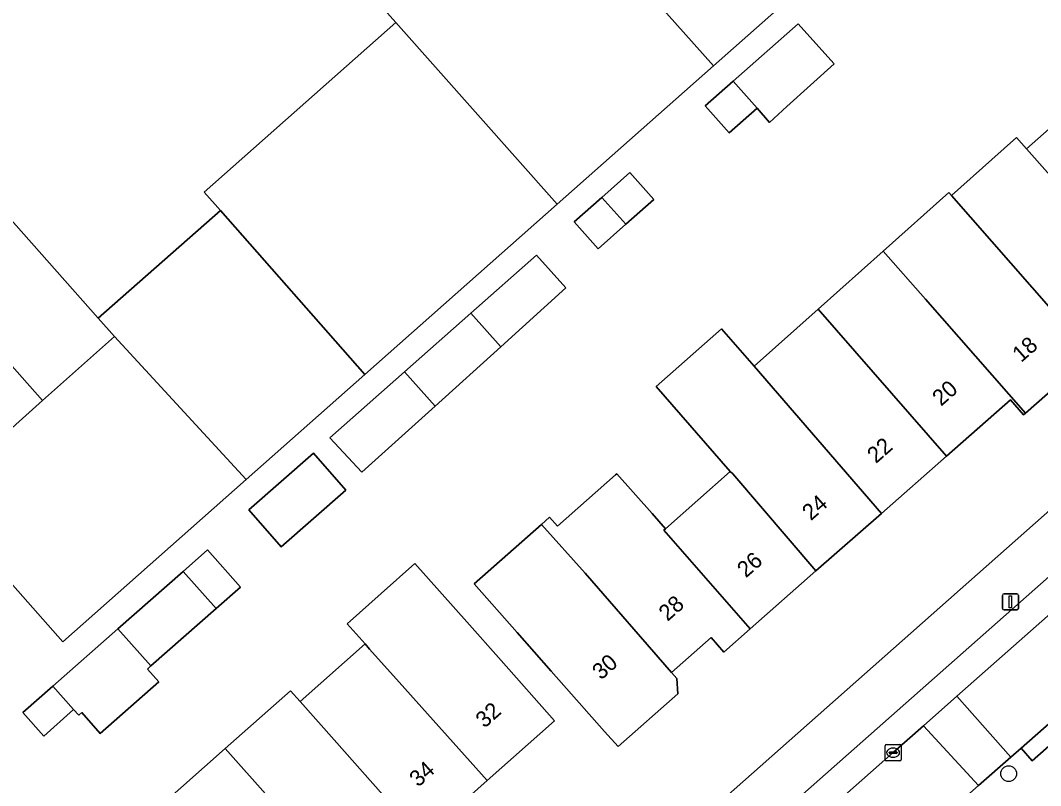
# Model space of a CAD drawing. Extents: x 157320 to 158835, y 386650 to 388491.
# Drawn here: x 157506.5 to 157569.8, y 387760.4 to 387807.9 of the extents above; entities that cross this region are included whole.
import ezdxf

# ---------------------------------------------------------------- set-up
doc = ezdxf.new("R2010")
doc.units = 0
for name, color, linetype in [('IMGEO_Boom', 7, 'Continuous'), ('IMGEO_Erf', 7, 'Continuous'), ('IMGEO_Kolk', 7, 'Continuous'), ('IMGEO_Lichtmast', 7, 'Continuous'), ('IMGEO_Pand', 7, 'Continuous'), ('IMGEO_Pand_nummerreeks', 7, 'Continuous'), ('IMGEO_Parkeervlak_open', 7, 'Continuous'), ('IMGEO_Rijbaan_lokaal_open', 7, 'Continuous'), ('IMGEO_Voetpad_open', 7, 'Continuous')]:
    doc.layers.add(name, color=color, linetype=linetype)

msp = doc.modelspace()

# ---------------------------------------------------------------- linework, layer by layer
at = {"layer": 'IMGEO_Boom'}
msp.add_circle((157567.808, 387761.126), 0.489, dxfattribs=at)
at = {"layer": 'IMGEO_Erf'}
for points in [[(157500.442, 387801.652), (157511.299, 387789.421), (157518.874, 387796.096), (157517.869, 387797.236), (157529.765, 387807.772), (157526.254, 387811.719), (157534.337, 387818.87), (157533.065, 387820.308), (157534.713, 387821.765), (157545.368, 387809.725), (157550.727, 387814.47), (157552.856, 387816.356), (157556.966, 387811.71), (157549.48, 387805.08), (157539.79, 387796.498), (157527.844, 387785.918), (157520.476, 387779.393), (157509.086, 387769.305), (157501.142, 387778.301), (157507.844, 387784.293), (157495.97, 387797.689)], [(157572.95, 387787.111), (157568.862, 387783.508), (157568.739, 387783.4), (157567.916, 387784.335), (157563.943, 387780.84), (157559.906, 387777.288), (157555.846, 387773.716), (157551.763, 387770.125), (157550.122, 387768.681), (157549.34, 387769.574), (157546.882, 387767.406), (157547.215, 387767.03), (157547.277, 387766.084), (157543.567, 387762.807), (157542.728, 387763.743), (157539.419, 387767.492), (157537.304, 387769.887), (157534.627, 387772.919), (157538.801, 387776.604), (157539.311, 387777.054), (157539.796, 387776.504), (157543.397, 387779.685), (157543.479, 387779.757), (157545.672, 387777.275), (157546.499, 387776.339), (157550.514, 387779.884), (157545.936, 387785.18), (157549.99, 387788.759), (157552.01, 387786.423), (157555.986, 387789.974), (157560.024, 387793.581), (157564.098, 387797.219), (157564.258, 387797.039), (157566.759, 387799.27), (157568.287, 387800.633), (157568.92, 387799.92), (157572.962, 387803.488)], [(157509.624, 387726.538), (157507.154, 387731.474), (157527.921, 387750), (157537.423, 387758.476), (157542.489, 387752.818), (157588.712, 387793.729)], [(157515.137, 387759.104), (157519.176, 387762.687), (157523.225, 387766.279), (157523.826, 387765.604), (157527.855, 387769.189), (157526.745, 387770.437), (157528.855, 387772.315), (157530.946, 387774.176), (157534.17, 387770.552), (157536.304, 387768.154), (157539.627, 387764.418), (157535.442, 387760.694), (157531.389, 387757.088)]]:
    msp.add_lwpolyline(points, dxfattribs=at)
for points in [[(157548.977, 387802.592), (157550.708, 387804.123), (157554.75, 387807.699), (157556.394, 387805.856), (157556.976, 387805.204), (157554.046, 387802.551), (157552.964, 387801.571), (157552.192, 387802.444), (157550.462, 387800.914)], [(157540.834, 387795.391), (157542.556, 387796.914), (157544.295, 387798.451), (157545.779, 387796.773), (157544.049, 387795.242), (157542.319, 387793.712)], [(157532.211, 387783.956), (157527.667, 387779.841), (157525.677, 387781.984), (157530.308, 387786.08), (157534.425, 387789.722), (157538.491, 387793.318), (157540.311, 387791.292), (157536.279, 387787.64)], [(157520.645, 387777.504), (157524.65, 387781.022), (157526.661, 387778.732), (157522.656, 387775.215)], [(157511.408, 387763.621), (157510.266, 387764.917), (157510.082, 387764.754), (157509.766, 387765.108), (157507.925, 387763.459), (157506.61, 387764.928), (157508.467, 387766.564), (157512.511, 387770.125), (157516.556, 387773.687), (157518.078, 387775.027), (157520.119, 387772.709), (157518.619, 387771.388), (157514.568, 387767.821), (157514.342, 387767.622), (157515.045, 387766.823)]]:
    msp.add_lwpolyline(points, close=True, dxfattribs=at)
at = {"layer": 'IMGEO_Kolk'}
for p, q in [((157560.211, 387762.932), (157561.063, 387762.932)), ((157560.136, 387762.006), (157560.136, 387762.858)), ((157560.395, 387762.426), (157560.395, 387762.438)), ((157560.833, 387762.389), (157560.435, 387762.389)), ((157560.438, 387762.475), (157560.836, 387762.475)), ((157560.624, 387762.712), (157560.649, 387762.712)), ((157560.879, 387762.438), (157560.879, 387762.426)), ((157561.137, 387762.858), (157561.137, 387762.006)), ((157561.063, 387761.932), (157560.211, 387761.932)), ((157560.647, 387762.152), (157560.622, 387762.152))]:
    msp.add_line(p, q, dxfattribs=at)
for points in [[(157560.211, 387762.932), (157561.063, 387762.932)], [(157560.136, 387762.006), (157560.136, 387762.858)], [(157561.137, 387762.858), (157561.137, 387762.006)], [(157561.063, 387761.932), (157560.211, 387761.932)]]:
    msp.add_lwpolyline(points, dxfattribs=at)
for centre, radius, start, end in [((157560.213, 387762.856), 0.0765, 91.55205, 178.44795), ((157560.213, 387762.856), 0.0765, 91.55205, 178.44795), ((157561.061, 387762.856), 0.0765, 1.55205, 88.44795), ((157561.061, 387762.856), 0.0765, 1.55205, 88.44795), ((157560.435, 387762.435), 0.0403, 85.87752, 175.75265), ((157560.432, 387762.425), 0.0366, 178.93798, 274.71019), ((157560.836, 387762.432), 0.043, 264.86636, 352.45326), ((157560.84, 387762.437), 0.0386, 1.73085, 96.63898), ((157560.213, 387762.008), 0.0765, 181.55205, 268.44795), ((157560.213, 387762.008), 0.0765, 181.55205, 268.44795), ((157561.061, 387762.008), 0.0765, 271.55205, 358.44795), ((157561.061, 387762.008), 0.0765, 271.55205, 358.44795)]:
    msp.add_arc(centre, radius, start, end, dxfattribs=at)
for centre, major_axis, ratio, start_param, end_param in [((157560.623, 387762.432), (-0.387, 0.002), 0.722429, 4.712389, 7.853982), ((157560.648, 387762.432), (-0.39, 0.002), 0.717154, 1.570796, 4.712389)]:
    msp.add_ellipse(centre, major_axis=major_axis, ratio=ratio, start_param=start_param, end_param=end_param, dxfattribs=at)
at = {"layer": 'IMGEO_Lichtmast'}
for p, q in [((157567.422, 387771.394), (157567.422, 387772.194)), ((157567.422, 387772.194), (157567.422, 387771.394)), ((157567.522, 387772.294), (157568.312, 387772.294)), ((157568.312, 387772.294), (157567.522, 387772.294)), ((157568.412, 387772.194), (157568.412, 387771.394)), ((157568.412, 387771.394), (157568.412, 387772.194)), ((157568.312, 387771.294), (157567.522, 387771.294)), ((157567.522, 387771.294), (157568.312, 387771.294))]:
    msp.add_line(p, q, dxfattribs=at)
msp.add_lwpolyline([(157567.842, 387772.169), (157567.992, 387772.169), (157567.992, 387771.419), (157567.842, 387771.419), (157567.842, 387772.169)], dxfattribs=at)
for centre, start, end in [((157567.522, 387772.194), 90, 180), ((157567.522, 387772.194), 90, 180), ((157568.312, 387772.194), 0, 90), ((157568.312, 387772.194), 360, 90), ((157567.522, 387771.394), 180, 270), ((157567.522, 387771.394), 180, 270), ((157568.312, 387771.394), 270, 0), ((157568.312, 387771.394), 270, 0)]:
    msp.add_arc(centre, 0.1, start, end, dxfattribs=at)
at = {"layer": 'IMGEO_Pand'}
for points in [[(157539.79, 387796.498), (157549.48, 387805.08), (157545.368, 387809.725), (157534.713, 387821.765), (157533.065, 387820.308), (157534.337, 387818.87), (157526.254, 387811.719), (157529.765, 387807.772)], [(157556.966, 387811.71), (157552.856, 387816.356), (157550.727, 387814.47), (157545.368, 387809.725), (157549.48, 387805.08)], [(157498.67, 387803.655), (157495.802, 387806.846), (157493.105, 387804.497), (157490.773, 387807.173), (157488.177, 387810.15), (157482.553, 387805.18), (157482.982, 387804.665), (157482.95, 387803.667), (157484.292, 387802.163), (157485.262, 387802.107), (157490.175, 387796.56), (157493.967, 387799.899), (157495.97, 387797.689), (157507.844, 387784.293), (157512.304, 387788.281), (157511.299, 387789.421), (157500.442, 387801.652), (157500, 387802.138)], [(157539.79, 387796.498), (157529.765, 387807.772), (157517.869, 387797.236), (157518.874, 387796.096), (157527.844, 387785.918)], [(157556.976, 387805.204), (157556.394, 387805.856), (157554.75, 387807.699), (157550.708, 387804.123), (157552.192, 387802.444), (157552.964, 387801.571), (157554.046, 387802.551)], [(157550.708, 387804.123), (157548.977, 387802.592), (157550.462, 387800.914), (157552.192, 387802.444)], [(157577.015, 387790.693), (157581.065, 387794.262), (157575.712, 387800.377), (157572.962, 387803.488), (157568.92, 387799.92), (157571.687, 387796.8)], [(157571.687, 387796.8), (157568.92, 387799.92), (157568.287, 387800.633), (157566.759, 387799.27), (157564.258, 387797.039), (157572.95, 387787.111), (157577.015, 387790.693)], [(157542.556, 387796.914), (157544.049, 387795.242), (157545.779, 387796.773), (157544.295, 387798.451)], [(157560.024, 387793.581), (157562.656, 387790.603), (157568.862, 387783.508), (157572.95, 387787.111), (157564.258, 387797.039), (157564.098, 387797.219)], [(157544.049, 387795.242), (157542.556, 387796.914), (157540.834, 387795.391), (157542.319, 387793.712)], [(157512.304, 387788.281), (157520.476, 387779.393), (157527.844, 387785.918), (157518.874, 387796.096), (157511.299, 387789.421)], [(157536.279, 387787.64), (157540.311, 387791.292), (157538.491, 387793.318), (157534.425, 387789.722)], [(157555.986, 387789.974), (157563.943, 387780.84), (157567.916, 387784.335), (157568.739, 387783.4), (157568.862, 387783.508), (157562.656, 387790.603), (157560.024, 387793.581)], [(157530.308, 387786.08), (157532.211, 387783.956), (157536.279, 387787.64), (157534.425, 387789.722)], [(157555.986, 387789.974), (157552.01, 387786.423), (157559.906, 387777.288), (157563.943, 387780.84)], [(157512.304, 387788.281), (157507.844, 387784.293), (157501.142, 387778.301), (157509.086, 387769.305), (157520.476, 387779.393)], [(157559.906, 387777.288), (157552.01, 387786.423), (157549.99, 387788.759), (157545.936, 387785.18), (157550.514, 387779.884), (157550.696, 387779.756), (157555.846, 387773.716)], [(157530.308, 387786.08), (157525.677, 387781.984), (157527.667, 387779.841), (157532.211, 387783.956)], [(157524.65, 387781.022), (157520.645, 387777.504), (157522.656, 387775.215), (157526.661, 387778.732)], [(157551.763, 387770.125), (157546.401, 387776.252), (157546.499, 387776.339), (157545.672, 387777.275), (157543.479, 387779.757), (157543.397, 387779.685), (157539.796, 387776.504), (157539.311, 387777.054), (157538.801, 387776.604), (157541.518, 387773.573), (157546.882, 387767.406), (157549.34, 387769.574), (157550.122, 387768.681)], [(157551.763, 387770.125), (157555.846, 387773.716), (157550.696, 387779.756), (157550.514, 387779.884), (157546.499, 387776.339), (157546.401, 387776.252)], [(157538.801, 387776.604), (157534.627, 387772.919), (157537.304, 387769.887), (157539.419, 387767.492), (157542.728, 387763.743), (157543.567, 387762.807), (157547.277, 387766.084), (157547.215, 387767.03), (157546.882, 387767.406), (157541.518, 387773.573)], [(157518.619, 387771.388), (157520.119, 387772.709), (157518.078, 387775.027), (157516.556, 387773.687)], [(157518.619, 387771.388), (157516.556, 387773.687), (157512.511, 387770.125), (157514.568, 387767.821)], [(157536.304, 387768.154), (157534.17, 387770.552), (157530.946, 387774.176), (157528.855, 387772.315), (157526.745, 387770.437), (157527.855, 387769.189), (157528.141, 387768.868), (157529.969, 387766.813), (157535.442, 387760.694), (157539.627, 387764.418)], [(157515.045, 387766.823), (157514.342, 387767.622), (157514.568, 387767.821), (157512.511, 387770.125), (157508.467, 387766.564), (157509.766, 387765.108), (157510.082, 387764.754), (157510.266, 387764.917), (157511.408, 387763.621)], [(157529.969, 387766.813), (157528.141, 387768.868), (157527.855, 387769.189), (157523.826, 387765.604), (157525.94, 387763.228), (157531.389, 387757.088), (157535.442, 387760.694)], [(157509.766, 387765.108), (157508.467, 387766.564), (157506.61, 387764.928), (157507.925, 387763.459)], [(157525.94, 387763.228), (157523.826, 387765.604), (157523.225, 387766.279), (157519.176, 387762.687), (157527.352, 387753.495), (157531.389, 387757.088)], [(157519.176, 387762.687), (157515.137, 387759.104), (157523.215, 387750), (157523.307, 387749.896), (157523.424, 387750), (157527.352, 387753.495)]]:
    msp.add_lwpolyline(points, close=True, dxfattribs=at)
at = {"layer": 'IMGEO_Parkeervlak_open'}
for points in [[(157588.426, 387789.301), (157587.678, 387788.628), (157584.028, 387785.488), (157545.406, 387751.353)], [(157544.555, 387748.211), (157546.578, 387750), (157560.665, 387762.456), (157562.533, 387764.107), (157564.601, 387765.934), (157575.15, 387775.257)]]:
    msp.add_lwpolyline(points, dxfattribs=at)
at = {"layer": 'IMGEO_Rijbaan_lokaal_open'}
for points in [[(157594.345, 387785.504), (157600.651, 387791.132), (157601.15, 387791.577), (157605.401, 387795.325), (157602.069, 387799.102), (157601.225, 387798.298), (157591.416, 387789.674), (157575.15, 387775.257), (157564.601, 387765.934), (157567.941, 387762.148), (157568.58, 387762.711), (157573.949, 387767.426), (157574.36, 387767.793), (157578.919, 387771.871)], [(157565.943, 387760.385), (157567.941, 387762.148), (157564.601, 387765.934), (157562.533, 387764.107)], [(157565.943, 387760.385), (157562.533, 387764.107), (157560.665, 387762.456), (157546.578, 387750), (157544.555, 387748.211), (157527.261, 387732.925), (157531.246, 387729.631), (157554.227, 387750)]]:
    msp.add_lwpolyline(points, close=True, dxfattribs=at)
at = {"layer": 'IMGEO_Voetpad_open'}
for points in [[(157646.248, 387841.686), (157643.93, 387839.695), (157630.109, 387827.61), (157601.031, 387802.263), (157599.159, 387800.624), (157598.489, 387801.366), (157597.99, 387801.918), (157595.341, 387799.617), (157595.424, 387799.532), (157592.161, 387796.66), (157588.712, 387793.729), (157542.489, 387752.818), (157540.918, 387751.636), (157539.075, 387750), (157516.533, 387729.995), (157509.624, 387726.538), (157517.619, 387710.56), (157521.634, 387712.569)], [(157545.406, 387751.353), (157584.028, 387785.488), (157587.678, 387788.628), (157588.426, 387789.301)], [(157574.36, 387767.793), (157573.949, 387767.426), (157574.635, 387766.645), (157569.266, 387761.93), (157568.58, 387762.711), (157567.941, 387762.148), (157565.943, 387760.385)]]:
    msp.add_lwpolyline(points, dxfattribs=at)
msp.add_lwpolyline([(157573.949, 387767.426), (157568.58, 387762.711), (157569.266, 387761.93), (157574.635, 387766.645)], close=True, dxfattribs=at)

# ---------------------------------------------------------------- texts
at = {"layer": 'IMGEO_Pand_nummerreeks'}
for s, rotation, p in [('18', 41.38835, (157568.584, 387786.622)), ('20', 41.33921, (157563.614, 387783.907)), ('22', 41.33921, (157559.572, 387780.351)), ('24', 41.33921, (157555.536, 387776.8)), ('26', 41.33921, (157551.498, 387773.248)), ('28', 41.40847, (157546.633, 387770.547)), ('30', 41.40847, (157542.507, 387766.908)), ('32', 41.66549, (157535.273, 387763.917)), ('34', 41.66549, (157531.157, 387760.254))]:
    msp.add_text(s, height=1, rotation=rotation, dxfattribs=at).set_placement(p)

doc.saveas('drawing.dxf')
